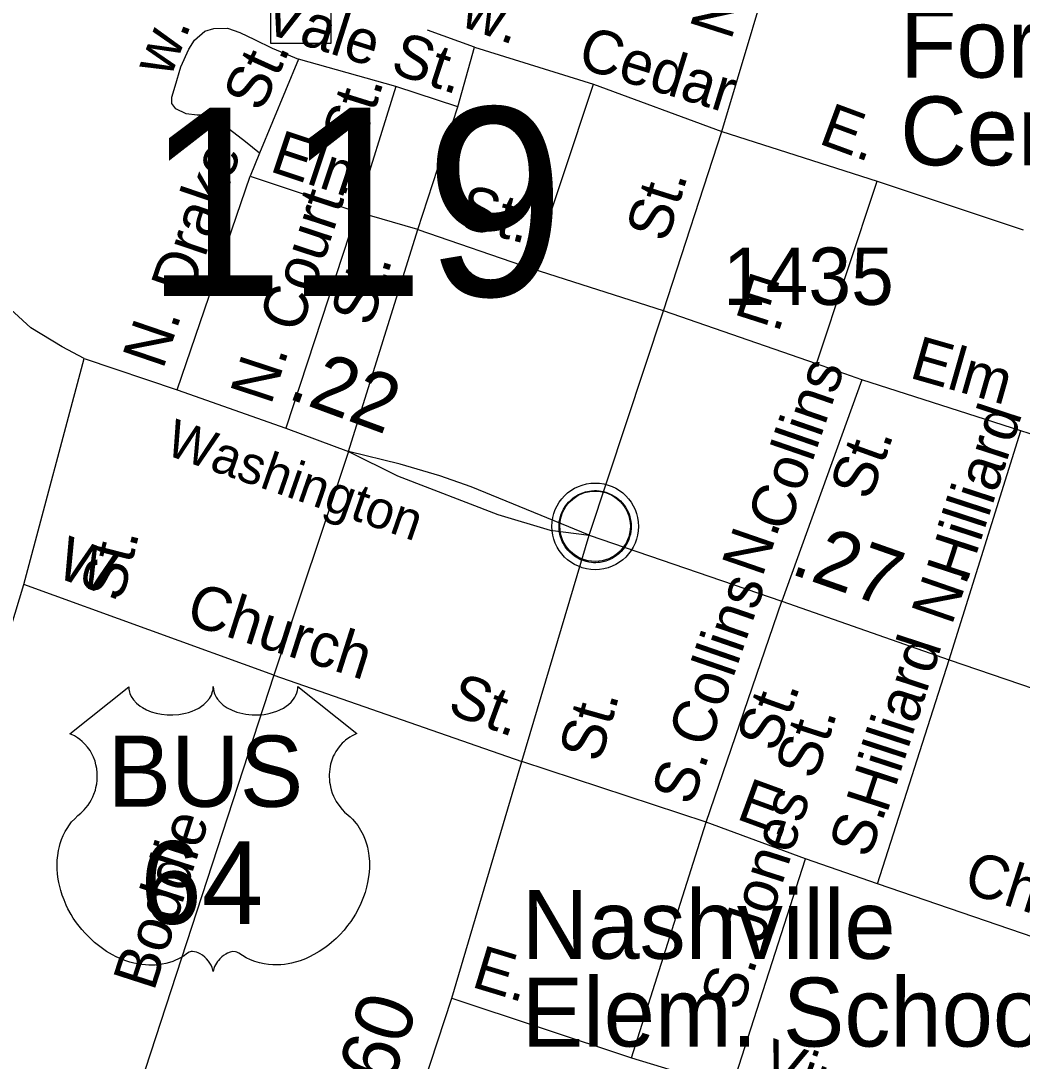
# Model space of a CAD drawing. Extents: x 2220236 to 2384410, y 720751 to 894131.
# Drawn here: x 2304806 to 2306986, y 810080 to 812345 of the extents above; entities that cross this region are included whole.
import ezdxf

# ---------------------------------------------------------------- set-up
doc = ezdxf.new("R2010")
doc.units = 0
for name, color, linetype in [('Exist Civil Demographics Community CELL', 7, 'Continuous'), ('Exist Cultural Cemetery Label', 7, 'Continuous'), ('Exist Cultural Church CELL', 7, 'Continuous'), ('Exist Cultural Educational Facility Elementary Label', 7, 'Continuous'), ('Exist Road Non-System Type 51', 7, 'Continuous'), ('Exist Road Non-System Type 51 Label', 7, 'Continuous'), ('Exist Road Primary NC Attributed', 7, 'Continuous'), ('Exist Road Primary US Attributed', 7, 'Continuous'), ('Exist Road Primary US Label', 7, 'Continuous'), ('Exist Road Primary US Mileage Hundredths English Label', 7, 'Continuous'), ('Exist Road Primary US Shield CELL', 7, 'Continuous'), ('Exist Road Primary US Shield Number Label', 7, 'Continuous'), ('Exist Road Secondary Mileage Hundredths English Label', 7, 'Continuous'), ('Exist Road Secondary Structure Standard Bridge Number Label', 7, 'Continuous'), ('Exist Road Secondary Type 51 Attributed', 7, 'Continuous'), ('Exist Road Secondary Type 51 Label', 7, 'Continuous'), ('Exist Road Secondary Type 51 Number Label', 7, 'Continuous')]:
    doc.layers.add(name, color=color, linetype=linetype)

msp = doc.modelspace()

# ---------------------------------------------------------------- linework, layer by layer
at = {"layer": 'Exist Civil Demographics Community CELL'}
msp.add_lwpolyline([(2305979.1, 811256.9), (2305980.1, 811262.5), (2305981.9, 811269), (2305984.8, 811276.2), (2305987.7, 811282), (2305991.1, 811287.7), (2305994.8, 811292.8), (2305998.8, 811297.2), (2306003.4, 811301.8), (2306008.9, 811306.4), (2306014.3, 811310), (2306019.2, 811312.9), (2306024.3, 811315.4), (2306029.7, 811317.7), (2306035.4, 811319.5), (2306039.7, 811320.6), (2306044.5, 811321.4), (2306048.7, 811322.1), (2306055, 811322.4), (2306059.5, 811322.2), (2306065.1, 811322), (2306070, 811321.3), (2306074.9, 811320.3), (2306080, 811318.9), (2306085.1, 811316.9), (2306091.8, 811314), (2306098, 811310.5), (2306103.1, 811307), (2306108.3, 811302.9), (2306111.6, 811299.8), (2306115.7, 811295.4), (2306119.6, 811290.7), (2306122.6, 811286.1), (2306125.8, 811281.1), (2306128.2, 811276), (2306130.3, 811271), (2306131.8, 811265.9), (2306133.1, 811261.4), (2306134.2, 811255.3), (2306134.8, 811250.6), (2306135.1, 811244.6), (2306134.9, 811238.8), (2306134.3, 811233.1), (2306133.4, 811227.6), (2306131.7, 811221.5), (2306129.9, 811215.6), (2306127.6, 811210.6), (2306124.4, 811204.6), (2306121.1, 811199.3), (2306117.7, 811194.6), (2306113.5, 811189.8), (2306108.2, 811184.9), (2306103.1, 811180.7), (2306098.1, 811177.3), (2306093.8, 811174.8), (2306087, 811171.6), (2306079.8, 811168.8), (2306073.9, 811167.4), (2306067.3, 811166.1), (2306062.9, 811165.6), (2306058.4, 811165.3), (2306052.8, 811165.3), (2306048.5, 811165.8), (2306042.9, 811166.5), (2306037, 811167.8), (2306032.4, 811169.1), (2306027.2, 811171), (2306022.6, 811173), (2306018.7, 811175.2), (2306011.9, 811179.3), (2306006.3, 811183.6), (2306001.4, 811188), (2305996.9, 811192.9), (2305993.8, 811196.9), (2305990.8, 811201), (2305986.7, 811208.1), (2305985, 811211.7), (2305983.2, 811215.7), (2305980.7, 811223.9), (2305979.1, 811230.9), (2305978.4, 811236.1), (2305978.1, 811242.4), (2305978, 811247.1), (2305978.6, 811253.6)], close=True, dxfattribs=at)
for centre, radius in [((2306056.7, 811244.4), 94.3), ((2306056.5, 811244.7), 76.7)]:
    msp.add_circle(centre, radius, dxfattribs=at)
at = {"layer": 'Exist Cultural Church CELL'}
msp.add_lwpolyline([(2305350.3, 812402.4), (2305407.3, 812402.5), (2305407.3, 812478.6), (2305375.3, 812478.6), (2305375.3, 812494.6), (2305407.3, 812494.6), (2305407.3, 812554.8), (2305423.3, 812554.8), (2305423.3, 812494.6), (2305455.3, 812494.6), (2305455.3, 812478.6), (2305423.3, 812478.6), (2305423.3, 812402.5), (2305480.9, 812402.4), (2305480.9, 812295.9), (2305350.3, 812295.9)], close=True, dxfattribs=at)
at = {"layer": 'Exist Road Non-System Type 51'}
for p, q in [((2305794, 812288.2), (2305691.6, 812325)), ((2305757.5, 812157.9), (2305794, 812288.2)), ((2305794, 812288.2), (2306052.8, 812207.1)), ((2305410.8, 812262.2), (2305325.9, 812057)), ((2305623, 812202.4), (2305410.8, 812262.2)), ((2305623, 812202.4), (2305537.9, 811929.6)), ((2305757.5, 812157.9), (2305623, 812202.4)), ((2305919.4, 811805.3), (2306052.8, 812207.1)), ((2306052.8, 812207.1), (2306332.4, 812104.5)), ((2305670.4, 811891), (2305757.5, 812157.9)), ((2306332.4, 812104.5), (2306670.8, 811995.9)), ((2305325.9, 812057), (2305305.3, 812007.1)), ((2305146.5, 811541.5), (2305305.3, 812007.1)), ((2305305.3, 812007.1), (2305537.9, 811929.6)), ((2306538.5, 811598.7), (2306670.8, 811995.9)), ((2306670.8, 811995.9), (2306988.1, 811890.4)), ((2305537.9, 811929.6), (2305383.1, 811458.1)), ((2305670.4, 811891), (2305537.9, 811929.6)), ((2305519.6, 811407.7), (2305670.4, 811891)), ((2305670.4, 811891), (2305919.4, 811805.3)), ((2306205.1, 811713.8), (2305919.4, 811805.3)), ((2306538.5, 811598.7), (2306205.1, 811713.8)), ((2306637.4, 811563.6), (2306538.5, 811598.7)), ((2306637.4, 811563.6), (2306463.3, 811081.3)), ((2306983.4, 811452.7), (2306637.4, 811563.6)), ((2306827.3, 810953.5), (2306983.4, 811452.7)), ((2307050.9, 811431.1), (2306983.4, 811452.7)), ((2305519.6, 811407.7), (2305357.4, 810920.5)), ((2305357.4, 810920.5), (2304813, 811118.1)), ((2306298, 810600.4), (2306463.3, 811081.3)), ((2306671.5, 810465.8), (2306827.3, 810953.5)), ((2305357.4, 810920.5), (2305020.3, 809889)), ((2305357.4, 810920.5), (2305896.9, 810732.6)), ((2306298, 810600.4), (2305896.9, 810732.6)), ((2306135.4, 810087.1), (2306298, 810600.4)), ((2306514.8, 810520.8), (2306298, 810600.4)), ((2306354.1, 810021.3), (2306514.8, 810520.8)), ((2306671.5, 810465.8), (2306514.8, 810520.8)), ((2307235.1, 810272.6), (2306671.5, 810465.8)), ((2305744.3, 810216.7), (2306135.4, 810087.1)), ((2306135.4, 810087.1), (2306354.1, 810021.3))]:
    msp.add_line(p, q, dxfattribs=at)
msp.add_lwpolyline([(2305325.9, 812057), (2305295.5, 812082), (2305260.3, 812108.7), (2305247.6, 812122.8), (2305235.7, 812131.9), (2305215.3, 812139.7), (2305189.9, 812139.7), (2305166, 812142.5), (2305143.5, 812153.8), (2305135.1, 812165), (2305135.1, 812179.1), (2305142.1, 812203), (2305154.8, 812245.3), (2305171.7, 812283.3), (2305184.3, 812303), (2305206.8, 812322.7), (2305226.5, 812328.3), (2305256.1, 812329.7), (2305282.8, 812319.9), (2305315.2, 812304.4), (2305353.2, 812286.1), (2305410.8, 812262.2)], dxfattribs=at)
at = {"layer": 'Exist Road Primary NC Attributed'}
msp.add_lwpolyline([(2304943.8, 811610.1), (2304896.2, 811635.3), (2304827.8, 811677), (2304792.2, 811709.7), (2304752.4, 811745.3), (2304718, 811784.9), (2304643.1, 811864), (2304574.3, 811953.3), (2304472.9, 812074.2), (2304408.1, 812147.3), (2304369.7, 812185), (2304321.2, 812242.4), (2304275, 812288.6), (2304165.6, 812396.7), (2304007.3, 812544.2), (2303954.8, 812594)], dxfattribs=at)
at = {"layer": 'Exist Road Primary US Attributed'}
for points in [[(2304403.5, 809735.1), (2304639.3, 810546.7), (2304813, 811118.1), (2304943.8, 811610.1)], [(2304943.8, 811610.1), (2305146.5, 811541.5), (2305383.1, 811458.1), (2305519.6, 811407.7)], [(2305519.6, 811407.7), (2305626.4, 811354.3), (2305844.7, 811270.1), (2305958.8, 811235.9), (2306043.4, 811225.4)], [(2306043.4, 811225.4), (2305787, 811330.9), (2305718.8, 811354.2), (2305632.1, 811380), (2305519.6, 811407.7)], [(2306043.4, 811225.4), (2306463.3, 811081.3), (2306827.3, 810953.5), (2307073.8, 810869.7), (2307171.4, 810838), (2307215, 810830.9), (2307251.8, 810828), (2307301.4, 810823.6), (2307392.6, 810822.9)]]:
    msp.add_lwpolyline(points, dxfattribs=at)
at = {"layer": 'Exist Road Primary US Shield CELL'}
msp.add_lwpolyline([(2305041.2, 810895.1), (2305041.5, 810889.8), (2305042.8, 810883.5), (2305043.8, 810880.2), (2305046.8, 810874), (2305051.6, 810866.6), (2305058.4, 810859.4), (2305066.1, 810853.1), (2305071.2, 810849.7), (2305080, 810845), (2305090, 810840.8), (2305101.1, 810837.7), (2305112.4, 810835.4), (2305124.8, 810834), (2305137, 810833.8), (2305150.2, 810834.8), (2305164.8, 810837.6), (2305171.5, 810839.3), (2305179.1, 810841.9), (2305186, 810844.8), (2305193.7, 810848.9), (2305199.9, 810852.9), (2305204.7, 810856.4), (2305211.5, 810862.9), (2305217, 810869.6), (2305219.2, 810873.4), (2305221.2, 810877.1), (2305223.9, 810884.8), (2305224.7, 810888.3), (2305225.2, 810895.4), (2305225.6, 810889.4), (2305226.3, 810885.7), (2305227.2, 810882), (2305228.8, 810878.2), (2305231.5, 810872.7), (2305234.5, 810868.1), (2305240.3, 810861.4), (2305243.8, 810858), (2305247.1, 810855.4), (2305255.8, 810849.4), (2305266.1, 810844.2), (2305271.1, 810842), (2305276.2, 810840.2), (2305282.8, 810838.2), (2305289.5, 810836.6), (2305296.2, 810835.5), (2305303, 810834.5), (2305310, 810833.9), (2305315.7, 810833.8), (2305322.7, 810833.9), (2305329.2, 810834.2), (2305335.8, 810835), (2305343.1, 810836.2), (2305348.9, 810837.5), (2305356.7, 810839.6), (2305363.6, 810842.1), (2305369.8, 810844.7), (2305377.8, 810848.9), (2305384.2, 810852.9), (2305388.9, 810856.7), (2305394.6, 810861.9), (2305399.9, 810868.1), (2305403, 810872.5), (2305405.2, 810877.2), (2305407.2, 810882), (2305408.5, 810887.2), (2305409.1, 810891.7), (2305409.2, 810895.5), (2305537.8, 810793.1), (2305534.8, 810791.9), (2305527.8, 810788.5), (2305522.3, 810785.2), (2305513.4, 810779), (2305509.6, 810775.6), (2305505.8, 810772), (2305502.3, 810768.2), (2305499.3, 810764.6), (2305495.5, 810759.5), (2305492.2, 810754.3), (2305488.9, 810748.6), (2305486.5, 810743.7), (2305482.6, 810733.3), (2305480.7, 810726.8), (2305479.5, 810721.2), (2305477.9, 810709.8), (2305477.6, 810704.3), (2305477.6, 810698.9), (2305477.9, 810693.2), (2305478.4, 810687.7), (2305479.4, 810682), (2305480.3, 810677), (2305481.9, 810670.9), (2305484.2, 810663.7), (2305487, 810656.8), (2305492.9, 810645.6), (2305500.4, 810634.2), (2305505.8, 810627.9), (2305511.1, 810622.4), (2305519.1, 810615.7), (2305523.4, 810611.9), (2305528.3, 810607), (2305536.3, 810597.6), (2305539.6, 810593.2), (2305542.9, 810588.3), (2305546, 810583.2), (2305549, 810577.7), (2305551.4, 810572.9), (2305555.9, 810561.9), (2305559.2, 810551.2), (2305560.8, 810545.6), (2305563.2, 810532.9), (2305564.1, 810526.7), (2305565.1, 810514.4), (2305565.1, 810499.5), (2305564, 810485.4), (2305561.3, 810468.9), (2305559.1, 810459), (2305555.7, 810447.5), (2305552.4, 810437.6), (2305546.6, 810422.9), (2305541.4, 810412.3), (2305534.6, 810399.8), (2305530, 810392.3), (2305524.6, 810384.2), (2305517.8, 810375), (2305509.9, 810365.1), (2305500.4, 810354.7), (2305492.8, 810347), (2305482.7, 810338), (2305476.7, 810333), (2305468, 810326.5), (2305456.1, 810318.6), (2305444.5, 810311.8), (2305434.5, 810306.7), (2305425.7, 810302.9), (2305414.3, 810298.6), (2305395.3, 810293.4), (2305388.4, 810291.9), (2305380.2, 810290.7), (2305372.5, 810289.9), (2305365.1, 810289.5), (2305355.1, 810289.5), (2305345.1, 810290.2), (2305335.7, 810291.6), (2305325.9, 810293.7), (2305315.6, 810296.7), (2305306.3, 810300.4), (2305296.9, 810305), (2305281, 810315), (2305276.4, 810317.4), (2305273.8, 810318.1), (2305267.7, 810318.4), (2305261.9, 810317.2), (2305256, 810314.9), (2305252.4, 810313), (2305247.7, 810309.9), (2305244, 810307), (2305239.6, 810302.8), (2305236.6, 810299.3), (2305234.3, 810296.6), (2305229.8, 810289.5), (2305228.2, 810286.1), (2305226.5, 810281.8), (2305225.1, 810275.4), (2305223, 810283.5), (2305220.7, 810288.8), (2305217.9, 810293.4), (2305215.1, 810297.4), (2305210.6, 810302.6), (2305206.6, 810306.4), (2305201.7, 810310.4), (2305196.6, 810313.5), (2305192.4, 810315.6), (2305188.6, 810317.1), (2305184, 810318.2), (2305180.2, 810318.5), (2305177.1, 810318.4), (2305172.8, 810317.5), (2305167, 810313.3), (2305161.5, 810309.5), (2305155.5, 810305.7), (2305148.3, 810301.9), (2305143.1, 810299.5), (2305136.9, 810297.1), (2305129.6, 810294.7), (2305121.7, 810292.6), (2305113.6, 810291), (2305106.4, 810289.9), (2305098.7, 810289.2), (2305091.8, 810289), (2305084.6, 810289), (2305077.9, 810289.6), (2305070, 810290.2), (2305060.3, 810291.7), (2305052.3, 810293.5), (2305043.8, 810295.8), (2305035, 810298.5), (2305025.7, 810302.1), (2305014, 810307.2), (2305005.9, 810311.4), (2304993, 810318.7), (2304978, 810329.2), (2304966.6, 810338.3), (2304958.3, 810345.9), (2304946.1, 810358.3), (2304938.9, 810366.5), (2304927.6, 810381.1), (2304920.4, 810391.6), (2304915.7, 810399.4), (2304908.9, 810411.8), (2304905.2, 810419.7), (2304900.3, 810431), (2304896.5, 810441.5), (2304893.3, 810451.3), (2304891.6, 810457.6), (2304889.1, 810468.7), (2304887.6, 810476.5), (2304886.2, 810487.2), (2304885.4, 810498.5), (2304885.3, 810508.9), (2304885.5, 810517.6), (2304886.5, 810527.7), (2304888.2, 810538.4), (2304890.3, 810547.6), (2304892.1, 810554.2), (2304894.9, 810562.3), (2304898.5, 810571.2), (2304902.7, 810579.7), (2304906.8, 810586.7), (2304911.9, 810594.3), (2304916.9, 810600.8), (2304923.5, 810607.9), (2304930.3, 810614.5), (2304936.6, 810619.6), (2304944, 810626.9), (2304947.9, 810631.3), (2304952.6, 810637.4), (2304956.3, 810643.1), (2304959.2, 810648.2), (2304963.1, 810655.7), (2304965.5, 810661.4), (2304968.5, 810670), (2304969.9, 810676.1), (2304971.5, 810683.9), (2304972.5, 810691.3), (2304972.8, 810700.5), (2304972.6, 810708.1), (2304971.6, 810717), (2304969.9, 810725.5), (2304967.9, 810732.9), (2304964.7, 810741.5), (2304961.8, 810747.7), (2304956.9, 810756.1), (2304951.4, 810763.9), (2304945.8, 810770.3), (2304940.1, 810776), (2304934.6, 810780.3), (2304929.4, 810784), (2304922.9, 810788), (2304916.6, 810791.1), (2304912.6, 810792.7)], close=True, dxfattribs=at)
at = {"layer": 'Exist Road Secondary Type 51 Attributed'}
for points in [[(2306043.4, 811225.4), (2306205.1, 811713.8), (2306332.4, 812104.5), (2306467, 812553.4), (2306532.9, 812735.9), (2306572.9, 812874.8), (2306606.4, 813018), (2306626.4, 813140.9), (2306656.4, 813342.9), (2306659.5, 813406.8), (2306662.9, 813476)], [(2305326, 808931.8), (2305337, 808982.6), (2305420.7, 809229.7), (2305484, 809429.6), (2305574.7, 809699.2), (2305744.3, 810216.7), (2305896.9, 810732.6), (2306043.4, 811225.4)]]:
    msp.add_lwpolyline(points, dxfattribs=at)

# ---------------------------------------------------------------- texts
at = {"layer": 'Exist Cultural Cemetery Label'}
for s, p in [('Forest Hill', (2306720.7, 812221.7)), ('Cemetery', (2306720.7, 812030.7))]:
    msp.add_text(s, height=150, dxfattribs=at).set_placement(p)
at = {"layer": 'Exist Cultural Educational Facility Elementary Label'}
for s, p in [('Nashville', (2305896.9, 810302.7)), ('Elem. School', (2305896.9, 810111.7))]:
    msp.add_text(s, height=150, dxfattribs=at).set_placement(p)
at = {"layer": 'Exist Road Non-System Type 51 Label'}
for s, rotation, p in [('Vale', 342.3569, (2305328.1, 812322.1)), ('w.', 340.2319, (2305759.3, 812335.5)), ('w.', 68.8093, (2305131.9, 812219.7)), ('Cedar', 342.9042, (2306014.5, 812245.1)), ('St.', 341.6939, (2305607.8, 812233.2)), ('St.', 65.6793, (2305330, 812143.7)), ('St.', 72.6749, (2305550.7, 812064.8)), ('E.', 339.7224, (2306540.3, 812079.1)), ('Elm', 341.5723, (2305345.3, 812018.7)), ('Drake', 71.167, (2305177.4, 811741.3)), ('Court.', 71.8243, (2305413.9, 811663)), ('St.', 345.7593, (2305754.1, 811898.1)), ('St.', 72.6708, (2305569.3, 811677.1)), ('E.', 342.2878, (2306355.5, 811707.2)), ('N.', 71.167, (2305115.5, 811584.4)), ('Elm', 344.0355, (2306738.1, 811568.9)), ('N.', 71.8243, (2305350.5, 811506.6)), ('Collins', 70.9293, (2306475.8, 811229)), ('Hilliard', 71.9147, (2306866.4, 811120.9)), ('St.', 70.2416, (2306654.7, 811298.1)), ('N.', 70.9293, (2306420.1, 811131.6)), ('W.', 339.8601, (2304877.9, 811135.8)), ('Collins', 70.9293, (2306303.6, 810759)), ('N.', 70.9293, (2306832.6, 811026.7)), ('Church', 342.3718, (2305161.9, 811033.7)), ('Hilliard', 71.9147, (2306691.6, 810617.2)), ('St.', 339.839, (2305731.6, 810838.7)), ('St.', 70.2416, (2306451.2, 810749.7)), ('S. Jones St.', 72.1661, (2306374.4, 810186)), ('S.', 70.9293, (2306266.7, 810633.4)), ('E.', 339.9076, (2306361.2, 810608.4)), ('Boddie', 72.122, (2305095.8, 810230)), ('S.', 70.8929, (2306653.1, 810518.7)), ('Church', 342.3718, (2306854.5, 810449.6)), ('E.', 343.1491, (2305784.6, 810242.5)), ('Virginia', 340.57, (2306412.1, 810040.9))]:
    msp.add_text(s, height=95, rotation=rotation, dxfattribs=at).set_placement(p)
at = {"layer": 'Exist Road Primary US Label'}
for s, height, rotation, p in [('Washington', 82.02, 340.8104, (2305116.6, 811402.2)), ('St.', 95, 75.8133, (2305026.7, 811079.2))]:
    msp.add_text(s, height=height, rotation=rotation, dxfattribs=at).set_placement(p)
at = {"layer": 'Exist Road Primary US Mileage Hundredths English Label'}
for s, rotation, p in [('.22', 339.7341, (2305383.4, 811524.6)), ('.27', 340.6627, (2306478.2, 811142.3))]:
    msp.add_text(s, height=125, rotation=rotation, dxfattribs=at).set_placement(p)
at = {"layer": 'Exist Road Primary US Shield Number Label'}
for s, height, p in [('BUS', 155, (2304994.9, 810633.8)), ('64', 180, (2305066.3, 810378.9))]:
    msp.add_text(s, height=height, dxfattribs=at).set_placement(p)
at = {"layer": 'Exist Road Secondary Mileage Hundredths English Label'}
msp.add_text('.60', height=125, rotation=71.9926, dxfattribs=at).set_placement((2305599.1, 809979.3))
at = {"layer": 'Exist Road Secondary Structure Standard Bridge Number Label'}
msp.add_text('119', height=410.1, dxfattribs=at).set_placement((2305075.9, 811746.3))
at = {"layer": 'Exist Road Secondary Type 51 Label'}
for s, rotation, p in [('N.', 72.3214, (2306352.1, 812301.1)), ('St.', 72.4479, (2306212.2, 811859.9)), ('St.', 74.2142, (2306067.5, 810727.4))]:
    msp.add_text(s, height=95, rotation=rotation, dxfattribs=at).set_placement(p)
at = {"layer": 'Exist Road Secondary Type 51 Number Label'}
msp.add_text('1435', height=125, dxfattribs=at).set_placement((2306334.9, 811726.7))

doc.saveas('drawing.dxf')
